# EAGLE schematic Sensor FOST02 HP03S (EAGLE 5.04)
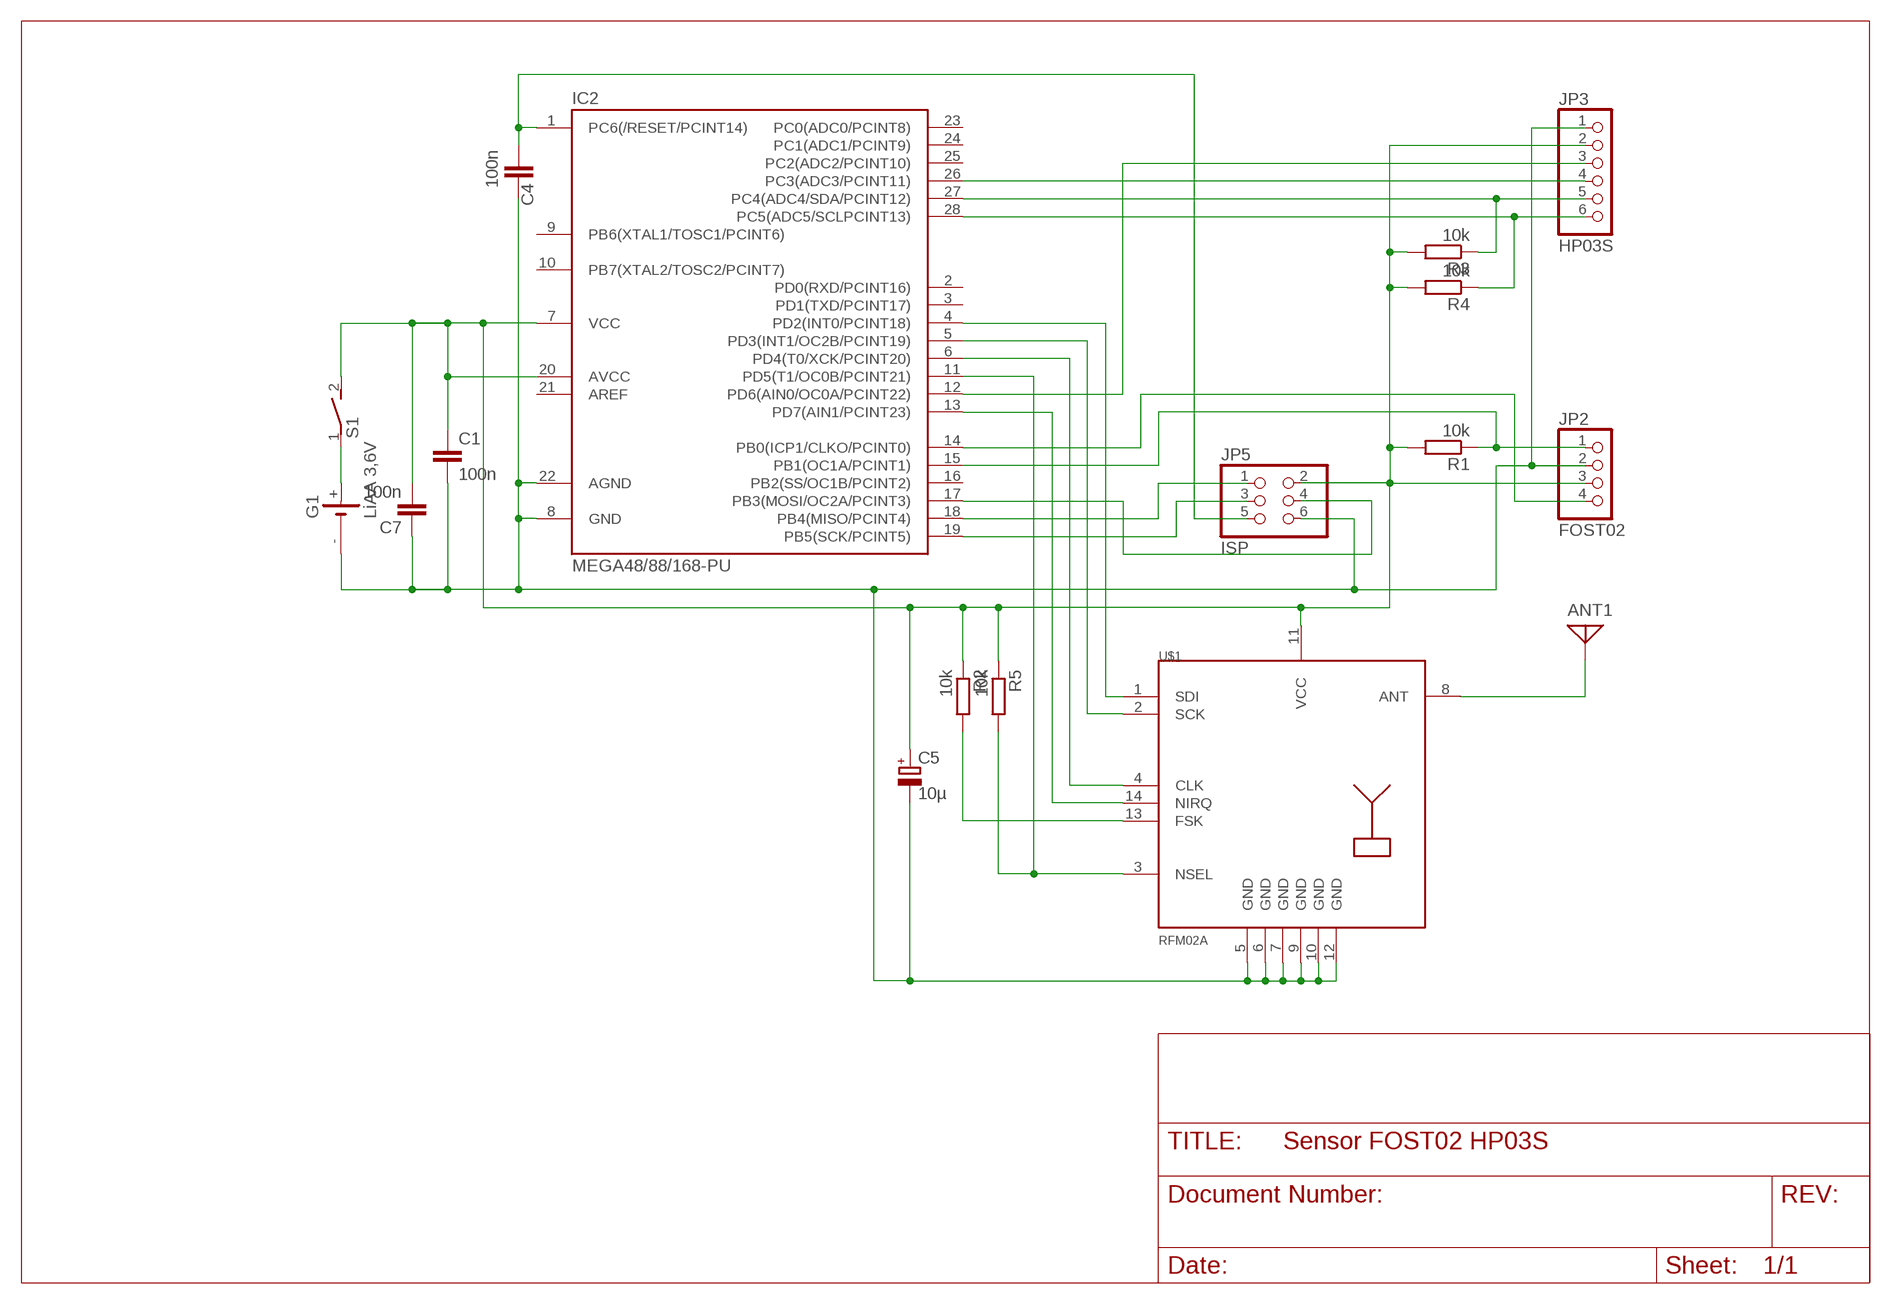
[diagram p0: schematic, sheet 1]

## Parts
ANT1  ANTENNA  [PAD-01]
C1  100n  C-EU025-024X044  [C025-024X044]
C4  100n  C-EU025-024X044  [C025-024X044]
C5  10µ  CPOL-EUE2-5  [E2-5]
C7  100n  C-EU025-024X044  [C025-024X044]
G1  LiAA 3,6V  SL-160AA/PT  [SL-160AA/PT]
IC2  MEGA48/88/168-PU  [DIL28-3]
JP2  FOST02  PINHD-1X4  [1X04]
JP3  HP03S  PINHD-1X6  [1X06]
JP5  ISP  PINHD-2X3  [2X03]
R1  10k  R-EU_0207/10  [0207/10]
R2  10k  R-EU_0207/10  [0207/10]
R3  10k  R-EU_0207/10  [0207/10]
R4  10k  R-EU_0207/10  [0207/10]
R5  10k  R-EU_0207/10  [0207/10]
S1  DS01E  [DS-01]
U$1  RFM02A  [RFM1]

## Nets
N$1: C4.1 IC2.1(PC6(/RESET/PCINT14)) JP5.5
N$2: IC2.15(PB1(OC1A/PCINT1)) JP2.1 R1.1
N$3: IC2.18(PB4(MISO/PCINT4)) JP5.1
N$4: IC2.4(PD2(INT0/PCINT18)) U$1.1(SDI)
N$5: IC2.6(PD4(T0/XCK/PCINT20)) U$1.4(CLK)
N$6: IC2.14(PB0(ICP1/CLKO/PCINT0)) JP2.4
N$7: ANT1.1 U$1.8(ANT)
N$8: R2.2 U$1.13(FSK)
N$9: C1.2 C4.2 C5.- C7.1 G1.- IC2.8(GND) IC2.22(AGND) JP2.2 JP3.1 JP5.6 U$1.5(GND) U$1.6(GND) U$1.7(GND) U$1.9(GND) U$1.10(GND) U$1.12(GND)
N$10: IC2.5(PD3(INT1/OC2B/PCINT19)) U$1.2(SCK)
N$11: IC2.19(PB5(SCK/PCINT5)) JP5.3
N$12: IC2.17(PB3(MOSI/OC2A/PCINT3)) JP5.4
N$13: IC2.13(PD7(AIN1/PCINT23)) U$1.14(NIRQ)
N$14: IC2.11(PD5(T1/OC0B/PCINT21)) R5.2 U$1.3(NSEL)
N$15: C1.1 C5.+ C7.2 IC2.7(VCC) IC2.20(AVCC) JP2.3 JP3.2 JP5.2 R1.2 R2.1 R3.2 R4.2 R5.1 S1.2 U$1.11(VCC)
N$16: G1.+ S1.1
N$21: IC2.28(PC5(ADC5/SCLPCINT13)) JP3.6 R4.1
N$22: IC2.27(PC4(ADC4/SDA/PCINT12)) JP3.5 R3.1
N$23: IC2.26(PC3(ADC3/PCINT11)) JP3.4
N$24: IC2.12(PD6(AIN0/OC0A/PCINT22)) JP3.3
Unconnected: G1.-@1(-) IC2.2(PD0(RXD/PCINT16)) IC2.3(PD1(TXD/PCINT17)) IC2.9(PB6(XTAL1/TOSC1/PCINT6)) IC2.10(PB7(XTAL2/TOSC2/PCINT7)) IC2.16(PB2(SS/OC1B/PCINT2)) IC2.21(AREF) IC2.23(PC0(ADC0/PCINT8)) IC2.24(PC1(ADC1/PCINT9)) IC2.25(PC2(ADC2/PCINT10))

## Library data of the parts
ANT1 = discrete:ANTENNA: Antenna
C1 C4 C7 = rcl:C-EU: CAPACITOR, European symbol
C5 = rcl:CPOL-EU: POLARIZED CAPACITOR, European symbol
G1 = battery:SL-160AA/PT: LI BATTERY Sonnenschein
IC2 = avr-4:MEGA48/88/168-PU
JP2 = pinhead:PINHD-1X4: PIN HEADER
JP3 = pinhead:PINHD-1X6: PIN HEADER
JP5 = pinhead:PINHD-2X3: PIN HEADER
R1-R5 = rcl:R-EU_: RESISTOR, European symbol
S1 = switch-dil:DS01E: DIL/CODE SWITCH
U$1 = RFMxx:RFM02A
